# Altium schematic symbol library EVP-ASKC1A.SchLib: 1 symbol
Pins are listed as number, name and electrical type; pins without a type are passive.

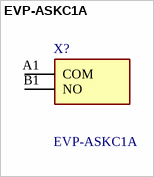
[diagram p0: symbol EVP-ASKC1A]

## EVP-ASKC1A
designator X?
Tactile Switches 3N 6x6.1x5mm 1.3mm Travel Black; Manufacturer_Name: Panasonic; Geometry.Height: 5.2mm
footprint EVPASKC1A
pins: A1 COM, B1 NO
